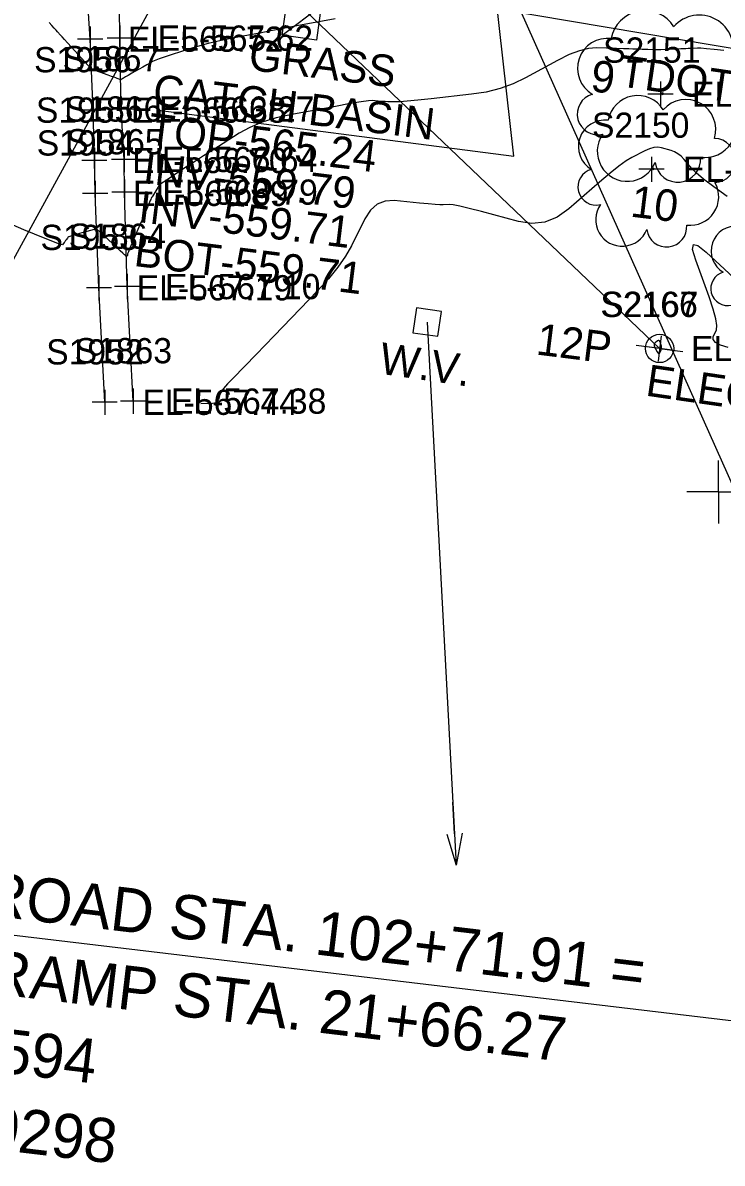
# Model space of a CAD drawing. Extents: x 1724534 to 1727318, y 657156 to 660047.
# Drawn here: x 1725389.5 to 1725500.6, y 658393.5 to 658574.4 of the extents above; entities that cross this region are included whole.
import ezdxf

# ---------------------------------------------------------------- set-up
doc = ezdxf.new("R2010")
doc.units = 0
for name, color, linetype in [('SURVEY - CENTERLINE - Preliminary Text', 7, 'Continuous'), ('SURVEY - CONTOURS - Intermediate with optional Text', 7, 'Continuous'), ('SURVEY - CONTROL - Grid', 7, 'Continuous'), ('SURVEY - DRAINAGE - Storm Sewer', 7, 'Continuous'), ('SURVEY - DRAINAGE - Storm Sewer - Points - Locators', 7, 'Continuous'), ('SURVEY - DRAINAGE - Storm Sewer Text', 7, 'Continuous'), ('SURVEY - MISCELLANEOUS - Bottom of MH and CB', 7, 'Continuous'), ('SURVEY - TRAFFIC CONTROL - Signs and Devices with Text', 7, 'Continuous'), ('SURVEY - TRANSPORTATION - Features', 7, 'Continuous'), ('SURVEY - TRANSPORTATION - Features - Points - Elevations', 7, 'Continuous'), ('SURVEY - TRANSPORTATION - Features - Points - Locators', 7, 'Continuous'), ('SURVEY - TRANSPORTATION - Features - Points - Numbers', 7, 'Continuous'), ('SURVEY - UTILITIES - Fiber Optic Cable (Underground) with Text', 7, 'Continuous'), ('SURVEY - UTILITIES - Overhead Wire Crossings', 7, 'Continuous'), ('SURVEY - UTILITIES - Poles and Miscellaneous - Points - Elevations', 7, 'Continuous'), ('SURVEY - UTILITIES - Poles and Miscellaneous - Points - Locators', 7, 'Continuous'), ('SURVEY - UTILITIES - Poles and Miscellaneous - Points - Numbers', 7, 'Continuous'), ('SURVEY - UTILITIES - Poles and Miscellaneous with Text', 7, 'Continuous'), ('SURVEY - UTILITIES - Water with Text', 7, 'Continuous'), ('SURVEY - VEGETATION - Features - Points - Elevations', 7, 'Continuous'), ('SURVEY - VEGETATION - Features - Points - Locators', 7, 'Continuous'), ('SURVEY - VEGETATION - Features - Points - Numbers', 7, 'Continuous'), ('SURVEY - VEGETATION - Features with Text', 7, 'Continuous')]:
    doc.layers.add(name, color=color, linetype=linetype)

msp = doc.modelspace()

# ---------------------------------------------------------------- linework, layer by layer
at = {"layer": 'SURVEY - CENTERLINE - Preliminary Text'}
for p, q in [((1725435.03, 658622.86), (1725332.93, 658436.26)), ((1725332.93, 658436.26), (1725534.5, 658412.24))]:
    msp.add_line(p, q, dxfattribs=at)
at = {"layer": 'SURVEY - CONTOURS - Intermediate with optional Text'}
for points in [[(1725439.15, 658575.09), (1725433.07, 658573.95), (1725430.9, 658573.53), (1725428.94, 658573.16), (1725427.18, 658572.82), (1725425.63, 658572.52), (1725421.77, 658571.77), (1725420.35, 658571.47), (1725418.98, 658571.15), (1725417.66, 658570.79), (1725416.39, 658570.41), (1725413.08, 658569.34), (1725411.97, 658568.99), (1725411.16, 658568.72), (1725410.63, 658568.53), (1725410.39, 658568.43), (1725410.12, 658568.28), (1725409.95, 658568.18), (1725409.64, 658568.01), (1725409.2, 658567.76), (1725408.61, 658567.42), (1725406.85, 658566.43), (1725406.27, 658566.1), (1725405.83, 658565.85), (1725405.54, 658565.68), (1725405.4, 658565.6), (1725405.07, 658565.42), (1725404.49, 658565.63), (1725404.31, 658565.69), (1725404.02, 658565.8), (1725403.61, 658565.94), (1725403.1, 658566.12), (1725400.43, 658567.07), (1725397.24, 658570.59), (1725396.62, 658571.28), (1725396.13, 658571.82), (1725395.76, 658572.23), (1725395.52, 658572.5), (1725395.04, 658573.02), (1725394.82, 658573.27), (1725394.52, 658573.59), (1725394.14, 658574.01), (1725393.69, 658574.51)], [(1725500.88, 658570.04), (1725499.33, 658570.22), (1725498.12, 658570.34), (1725497.22, 658570.41), (1725496.66, 658570.42), (1725495.58, 658570.37), (1725495.18, 658570.36), (1725494.8, 658570.34), (1725494.42, 658570.32), (1725494.05, 658570.31), (1725493.08, 658570.27), (1725492.73, 658570.25), (1725492.38, 658570.24), (1725492.04, 658570.22), (1725491.7, 658570.21), (1725490.83, 658570.17), (1725490.51, 658570.16), (1725490.19, 658570.16), (1725489.88, 658570.16), (1725489.57, 658570.17), (1725488.76, 658570.2), (1725488.46, 658570.21), (1725488.16, 658570.22), (1725487.86, 658570.23), (1725487.57, 658570.24), (1725486.8, 658570.27), (1725486.39, 658570.28), (1725485.77, 658570.3), (1725484.91, 658570.33), (1725483.83, 658570.37), (1725480.66, 658570.48), (1725479.38, 658570.39), (1725477.92, 658570.02), (1725476.28, 658569.39), (1725474.46, 658568.48), (1725469.37, 658565.71), (1725467.41, 658564.77), (1725465.32, 658564.02), (1725463.11, 658563.46), (1725460.78, 658563.1), (1725454.4, 658562.39), (1725452.25, 658562.16), (1725450.59, 658562), (1725449.41, 658561.91), (1725448.72, 658561.89), (1725447.52, 658561.92), (1725447.08, 658561.94), (1725446.68, 658561.96), (1725446.3, 658561.98), (1725445.95, 658562.01), (1725445.06, 658562.1), (1725444.44, 658562.07), (1725443.26, 658561.91), (1725441.5, 658561.62), (1725439.19, 658561.19), (1725432.25, 658559.89), (1725429.77, 658559.34), (1725427.56, 658558.66), (1725425.6, 658557.85), (1725423.9, 658556.92), (1725419.7, 658554.26), (1725418.23, 658553.32), (1725416.94, 658552.5), (1725415.85, 658551.79), (1725414.96, 658551.2), (1725412.12, 658549.31), (1725411.62, 658548.98), (1725411.32, 658548.77), (1725411.21, 658548.7), (1725411.2, 658548.67), (1725411.17, 658548.63), (1725411.1, 658548.51), (1725410.98, 658548.32), (1725410.82, 658548.06), (1725410.33, 658547.27), (1725410.17, 658547.01), (1725410.05, 658546.83), (1725409.98, 658546.72), (1725409.96, 658546.68), (1725409.96, 658546.68), (1725409.93, 658546.62), (1725409.85, 658546.43), (1725409.72, 658546.12), (1725409.53, 658545.69), (1725408.97, 658544.36), (1725408.74, 658543.82), (1725408.47, 658543.19), (1725408.16, 658542.48), (1725407.82, 658541.67), (1725406.85, 658539.41), (1725406.53, 658538.66), (1725406.31, 658538.12), (1725406.18, 658537.79), (1725406.13, 658537.66), (1725406.14, 658537.59), (1725406.14, 658537.56), (1725406.13, 658537.54), (1725406.12, 658537.51), (1725406.1, 658537.48), (1725405.98, 658537.36), (1725405.82, 658537.51), (1725405.7, 658537.62), (1725405.43, 658537.87), (1725404.99, 658538.28), (1725404.4, 658538.83), (1725401.25, 658541.76), (1725399.31, 658541.21), (1725398.91, 658541.1), (1725398.55, 658541), (1725398.24, 658540.91), (1725397.96, 658540.83), (1725397.26, 658540.63), (1725397.02, 658540.55), (1725396.83, 658540.47), (1725396.69, 658540.38), (1725396.6, 658540.28), (1725396.41, 658540.01), (1725396.33, 658539.91), (1725396.26, 658539.8), (1725396.18, 658539.69), (1725396.09, 658539.56), (1725395.85, 658539.23), (1725395.11, 658539.41), (1725393.06, 658540.2), (1725389.7, 658541.59), (1725385.03, 658543.58)], [(1725501.41, 658546.9), (1725499.28, 658548.42), (1725497.63, 658549.66), (1725496.45, 658550.62), (1725495.76, 658551.31), (1725494.53, 658552.78), (1725494.06, 658553.28), (1725493.56, 658553.68), (1725493.03, 658553.98), (1725492.47, 658554.19), (1725490.96, 658554.61), (1725490.37, 658554.69), (1725489.73, 658554.64), (1725489.04, 658554.46), (1725488.3, 658554.13), (1725486.26, 658553.09), (1725485.36, 658552.55), (1725484.2, 658551.71), (1725482.78, 658550.57), (1725481.1, 658549.14), (1725476.25, 658544.91), (1725474.39, 658543.59), (1725472.43, 658542.82), (1725470.38, 658542.6), (1725468.23, 658542.91), (1725462.39, 658544.48), (1725460.42, 658544.99), (1725458.91, 658545.35), (1725457.86, 658545.56), (1725457.27, 658545.62), (1725456.29, 658545.57), (1725455.78, 658545.58), (1725454.99, 658545.62), (1725453.9, 658545.71), (1725452.53, 658545.84), (1725448.48, 658546.23), (1725447.06, 658546.16), (1725445.81, 658545.66), (1725444.74, 658544.71), (1725443.85, 658543.33), (1725441.73, 658539.05), (1725440.79, 658537.4), (1725439.58, 658535.66), (1725438.09, 658533.82), (1725436.32, 658531.9), (1725429.45, 658524.78), (1725426.57, 658521.82), (1725422.91, 658518.05), (1725422.06, 658517.15), (1725421.42, 658516.42), (1725421.01, 658515.86), (1725420.82, 658515.47), (1725420.59, 658514.68), (1725420.47, 658514.41), (1725420.27, 658514.22), (1725419.99, 658514.1), (1725419.63, 658514.06), (1725417.78, 658514.01)], [(1725496.39, 658536.76), (1725495.9, 658538.47), (1725496.02, 658539.26), (1725496.74, 658539.12), (1725498.07, 658538.06), (1725502.43, 658533.99)], [(1725501.52, 658522.9), (1725500.34, 658523.32), (1725499.55, 658523.74), (1725499.15, 658524.17), (1725499.15, 658524.6), (1725499.68, 658525.74), (1725499.76, 658526.39), (1725499.58, 658527.48), (1725499.16, 658529), (1725498.5, 658530.95), (1725496.39, 658536.76)], [(1725490.89, 658522.57), (1725490.95, 658522.75), (1725490.97, 658522.93), (1725490.96, 658523.12), (1725490.91, 658523.31), (1725490.73, 658523.82), (1725490.65, 658523.97), (1725490.55, 658524.05), (1725490.44, 658524.05), (1725490.3, 658523.98), (1725489.93, 658523.69), (1725489.82, 658523.56), (1725489.78, 658523.39), (1725489.81, 658523.19), (1725489.9, 658522.95), (1725490.25, 658522.26), (1725490.37, 658522.06), (1725490.48, 658521.96), (1725490.58, 658521.98), (1725490.67, 658522.1), (1725490.89, 658522.57)]]:
    msp.add_lwpolyline(points, dxfattribs=at)
at = {"layer": 'SURVEY - CONTROL - Grid'}
for q in [(1725500, 658505), (1725495, 658500), (1725505, 658500), (1725500, 658495)]:
    msp.add_line((1725500, 658500), q, dxfattribs=at)
at = {"layer": 'SURVEY - DRAINAGE - Storm Sewer'}
msp.add_line((1725462.98, 658588.87), (1725518.53, 658464.57), dxfattribs=at)
at = {"layer": 'SURVEY - DRAINAGE - Storm Sewer - Points - Locators'}
for p, q in [((1725440.97, 658569.36), (1725440.97, 658569.86)), ((1725441.22, 658569.61), (1725440.72, 658569.61)), ((1725440.97, 658569.61), (1725440.97, 658569.61)), ((1725440.97, 658569.61), (1725440.97, 658569.61))]:
    msp.add_line(p, q, dxfattribs=at)
at = {"layer": 'SURVEY - DRAINAGE - Storm Sewer Text'}
msp.add_lwpolyline([(1725411.05, 658560.56), (1725467.53, 658553.31), (1725463.49, 658589.12)], dxfattribs=at)
at = {"layer": 'SURVEY - TRAFFIC CONTROL - Signs and Devices with Text'}
msp.add_line((1725430.72, 658572.47), (1725436.93, 658577.15), dxfattribs=at)
msp.add_lwpolyline([(1725430.72, 658572.47), (1725431.49, 658577.91), (1725436.93, 658577.15), (1725436.17, 658571.7)], close=True, dxfattribs=at)
at = {"layer": 'SURVEY - TRANSPORTATION - Features'}
for points in [[(1725407.05, 658514.42), (1725406.11, 658532.59), (1725405.69, 658547.58), (1725405.6, 658552.77), (1725405.16, 658560.76), (1725404.94, 658572.02), (1725404.9, 658577.02), (1725405.12, 658581.79), (1725407.36, 658588.68), (1725407.72, 658589.91), (1725413.38, 658589.19), (1725422.98, 658587.95), (1725437.86, 658586.06), (1725459.26, 658583.44), (1725464.53, 658582.74), (1725469.84, 658582.1), (1725479.42, 658580.9), (1725489.32, 658579.68), (1725509.01, 658577.31), (1725525.47, 658575.59), (1725525.74, 658575.98), (1725538.36, 658574.49), (1725538.14, 658573.13)], [(1725402.53, 658514.23), (1725401.62, 658532.4), (1725401.03, 658547.38), (1725400.89, 658552.59), (1725400.72, 658560.59), (1725400.22, 658571.85), (1725399.89, 658576.83)]]:
    msp.add_lwpolyline(points, dxfattribs=at)
at = {"layer": 'SURVEY - TRANSPORTATION - Features - Points - Locators'}
for p, q in [((1725400.22, 658573.85), (1725400.22, 658569.85)), ((1725404.94, 658574.02), (1725404.94, 658570.02)), ((1725402.22, 658571.85), (1725398.22, 658571.85)), ((1725406.94, 658572.02), (1725402.94, 658572.02)), ((1725400.72, 658562.59), (1725400.72, 658558.59)), ((1725405.16, 658562.76), (1725405.16, 658558.76)), ((1725402.72, 658560.59), (1725398.72, 658560.59)), ((1725407.16, 658560.76), (1725403.16, 658560.76)), ((1725400.89, 658554.59), (1725400.89, 658550.59)), ((1725405.6, 658554.77), (1725405.6, 658550.77)), ((1725402.89, 658552.59), (1725398.89, 658552.59)), ((1725407.6, 658552.77), (1725403.6, 658552.77)), ((1725401.03, 658549.38), (1725401.03, 658545.38)), ((1725405.69, 658549.58), (1725405.69, 658545.58)), ((1725403.03, 658547.38), (1725399.03, 658547.38)), ((1725407.69, 658547.58), (1725403.69, 658547.58)), ((1725401.62, 658534.4), (1725401.62, 658530.4)), ((1725406.11, 658534.59), (1725406.11, 658530.59)), ((1725403.62, 658532.4), (1725399.62, 658532.4)), ((1725408.11, 658532.59), (1725404.11, 658532.59)), ((1725402.53, 658516.23), (1725402.53, 658512.23)), ((1725407.05, 658516.42), (1725407.05, 658512.42)), ((1725404.53, 658514.23), (1725400.53, 658514.23)), ((1725409.05, 658514.42), (1725405.05, 658514.42))]:
    msp.add_line(p, q, dxfattribs=at)
at = {"layer": 'SURVEY - UTILITIES - Fiber Optic Cable (Underground) with Text'}
msp.add_line((1725528.95, 658565.81), (1725219.14, 658618.2), dxfattribs=at)
at = {"layer": 'SURVEY - UTILITIES - Overhead Wire Crossings'}
msp.add_line((1725320.87, 658684.66), (1725490.65, 658522.77), dxfattribs=at)
at = {"layer": 'SURVEY - UTILITIES - Poles and Miscellaneous - Points - Locators'}
for p, q in [((1725490.89, 658524.75), (1725490.41, 658520.78)), ((1725492.64, 658522.52), (1725488.67, 658523.01))]:
    msp.add_line(p, q, dxfattribs=at)
at = {"layer": 'SURVEY - UTILITIES - Poles and Miscellaneous with Text'}
for q in [(1725486.93, 658523.22), (1725494.37, 658522.31)]:
    msp.add_line((1725490.65, 658522.77), q, dxfattribs=at)
msp.add_circle((1725490.65, 658522.77), 2.25, dxfattribs=at)
at = {"layer": 'SURVEY - UTILITIES - Water with Text'}
for p, q in [((1725453.74, 658526.97), (1725453.74, 658526.97)), ((1725453.74, 658526.97), (1725458.36, 658440.78)), ((1725458.09, 658445.77), (1725457.82, 658450.77)), ((1725456.88, 658445.71), (1725458.36, 658440.78)), ((1725458.09, 658445.77), (1725458.36, 658440.78)), ((1725458.09, 658445.77), (1725458.36, 658440.78)), ((1725459.3, 658445.84), (1725458.36, 658440.78))]:
    msp.add_line(p, q, dxfattribs=at)
msp.add_lwpolyline([(1725452.05, 658529.23), (1725451.48, 658525.27), (1725455.44, 658524.7), (1725456.01, 658528.66), (1725452.05, 658529.23)], dxfattribs=at)
at = {"layer": 'SURVEY - VEGETATION - Features - Points - Locators'}
for p, q in [((1725490.81, 658565.12), (1725490.81, 658561.12)), ((1725492.81, 658563.12), (1725488.81, 658563.12)), ((1725489.38, 658553.2), (1725489.38, 658549.2)), ((1725491.38, 658551.2), (1725487.38, 658551.2))]:
    msp.add_line(p, q, dxfattribs=at)
at = {"layer": 'SURVEY - VEGETATION - Features with Text'}
for centre, radius in [((1725491.03, 658563.2), 0.166), ((1725489.58, 658551.28), 0.147)]:
    msp.add_circle(centre, radius, dxfattribs=at)
for centre, radius, start, end in [((1725488.31, 658570.95), 5.43, 31.9683, 169.4925), ((1725496.97, 658570.27), 5.4, 342.8641, 138.7026), ((1725482.4, 658567.21), 4.77, 82.9155, 239.7044), ((1725480.84, 658559.94), 3.27, 105.0317, 283.7773), ((1725487.18, 658558.11), 4.79, 31.9683, 169.4925), ((1725494.82, 658557.51), 4.76, 342.8641, 138.7026), ((1725481.96, 658554.81), 4.21, 82.9155, 239.7044), ((1725497.76, 658558.18), 5.13, 262.9581, 29.8037), ((1725485.52, 658554.04), 4.76, 145.0523, 338.472), ((1725499.25, 658552.6), 3.51, 273.117, 88.1173), ((1725493.53, 658552.77), 3.62, 187.671, 4.9902), ((1725480.58, 658548.4), 2.89, 105.0317, 283.7773), ((1725495.52, 658546.84), 4.52, 262.9581, 29.8037), ((1725484.71, 658543.19), 4.2, 145.0523, 338.472), ((1725491.78, 658542.07), 3.19, 187.671, 4.9902), ((1725502.75, 658538.25), 3.92, 82.9155, 239.7044), ((1725501.47, 658532.26), 2.69, 105.0317, 283.7773)]:
    msp.add_arc(centre, radius, start, end, dxfattribs=at)

# ---------------------------------------------------------------- texts
at = {"layer": 'SURVEY - CENTERLINE - Preliminary Text'}
for s, p in [('MURPHY ROAD STA. 102+71.91 =', (1725340.19, 658438.04)), ('I-440 OFF RAMP STA. 21+66.27', (1725338.74, 658425.87)), ('N 658622.8594', (1725337.29, 658413.71)), ('E 1725435.0298', (1725335.84, 658401.55))]:
    msp.add_text(s, height=7, rotation=353.2033, dxfattribs=at).set_placement(p)
at = {"layer": 'SURVEY - DRAINAGE - Storm Sewer Text'}
for s, p in [('CATCH BASIN', (1725410, 658561.36)), ('TOP-565.24', (1725409.24, 658555.19)), ('INV-559.79', (1725408.47, 658549.01)), ('INV-559.71', (1725407.71, 658542.84))]:
    msp.add_text(s, height=5, rotation=352.9589, dxfattribs=at).set_placement(p)
at = {"layer": 'SURVEY - MISCELLANEOUS - Bottom of MH and CB'}
msp.add_text('BOT-559.71', height=5, rotation=352.8716, dxfattribs=at).set_placement((1725407.03, 658535.88))
at = {"layer": 'SURVEY - TRANSPORTATION - Features - Points - Elevations'}
for s, p in [('EL-565.72', (1725406.22, 658569.85)), ('EL-565.62', (1725410.94, 658570.02)), ('EL-566.38', (1725406.72, 658558.59)), ('EL-566.27', (1725411.16, 658558.76)), ('EL-566.70', (1725406.89, 658550.59)), ('EL-566.64', (1725411.6, 658550.77)), ('EL-566.89', (1725407.03, 658545.38)), ('EL-566.79', (1725411.69, 658545.58)), ('EL-567.19', (1725407.62, 658530.4)), ('EL-567.10', (1725412.11, 658530.59)), ('EL-567.44', (1725408.53, 658512.23)), ('EL-567.38', (1725413.05, 658512.42))]:
    msp.add_text(s, height=4, dxfattribs=at).set_placement(p)
at = {"layer": 'SURVEY - TRANSPORTATION - Features - Points - Numbers'}
for s, p in [('S1956', (1725391.32, 658566.59)), ('S1867', (1725395.87, 658566.76)), ('S1955', (1725391.61, 658558.59)), ('S1866', (1725396.2, 658558.77)), ('S1954', (1725391.74, 658553.38)), ('S1865', (1725396.41, 658553.58)), ('S1953', (1725392.34, 658538.4)), ('S1864', (1725396.82, 658538.59)), ('S1952', (1725393.24, 658520.23)), ('S1863', (1725397.76, 658520.42))]:
    msp.add_text(s, height=4, dxfattribs=at).set_placement(p)
at = {"layer": 'SURVEY - UTILITIES - Poles and Miscellaneous - Points - Elevations'}
msp.add_text('EL-569.04', height=4, dxfattribs=at).set_placement((1725495.65, 658520.77))
msp.add_text('EL-569.04', height=4, dxfattribs=at).set_placement((1725495.65, 658520.77))
at = {"layer": 'SURVEY - UTILITIES - Poles and Miscellaneous - Points - Numbers'}
for s, p in [('S2166', (1725481.25, 658527.77)), ('S2167', (1725481.36, 658527.77))]:
    msp.add_text(s, height=4, dxfattribs=at).set_placement(p)
at = {"layer": 'SURVEY - UTILITIES - Poles and Miscellaneous with Text'}
for s, rotation, p in [('TDOT ITS', 351.7546, (1725484.05, 658564.41)), ('12P', 352.8641, (1725470.9, 658521.83)), ('ELECT', 351.7546, (1725488.28, 658515.31))]:
    msp.add_text(s, height=5, rotation=rotation, dxfattribs=at).set_placement(p)
at = {"layer": 'SURVEY - UTILITIES - Water with Text'}
msp.add_text('W.V.', height=5, rotation=351.7546, dxfattribs=at).set_placement((1725445.94, 658518.8))
at = {"layer": 'SURVEY - VEGETATION - Features - Points - Elevations'}
for s, p in [('EL-567.63', (1725495.81, 658561.12)), ('EL-568.17', (1725494.38, 658549.2))]:
    msp.add_text(s, height=4, dxfattribs=at).set_placement(p)
at = {"layer": 'SURVEY - VEGETATION - Features - Points - Numbers'}
for s, p in [('S2151', (1725481.68, 658568.12)), ('S2150', (1725479.92, 658556.2))]:
    msp.add_text(s, height=4, dxfattribs=at).set_placement(p)
at = {"layer": 'SURVEY - VEGETATION - Features with Text'}
for s, rotation, p in [('GRASS', 353.1032, (1725425.23, 658566.99)), ('9', 353.0264, (1725479.54, 658563.61)), ('10', 353.0264, (1725485.88, 658543.71))]:
    msp.add_text(s, height=5, rotation=rotation, dxfattribs=at).set_placement(p)

doc.saveas('drawing.dxf')
